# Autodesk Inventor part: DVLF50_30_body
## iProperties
Created: 2010-03
Part Number: DVLF50_30_body
Document SubType Name: Modeling
Designer: TB
Mass: 529.963 g
Surface Area: 1093.42 cm^2
Volume: 529.963 cm^3
Density: 1 g/cm^3
Author: TB
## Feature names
1. Kropp [Revolution]
2. Chamfer
3. Extrusion2
4. Hole1
5. Revolution2
6. Hole2
7. Fillet1
8. Extrusion3
9. Hole3
